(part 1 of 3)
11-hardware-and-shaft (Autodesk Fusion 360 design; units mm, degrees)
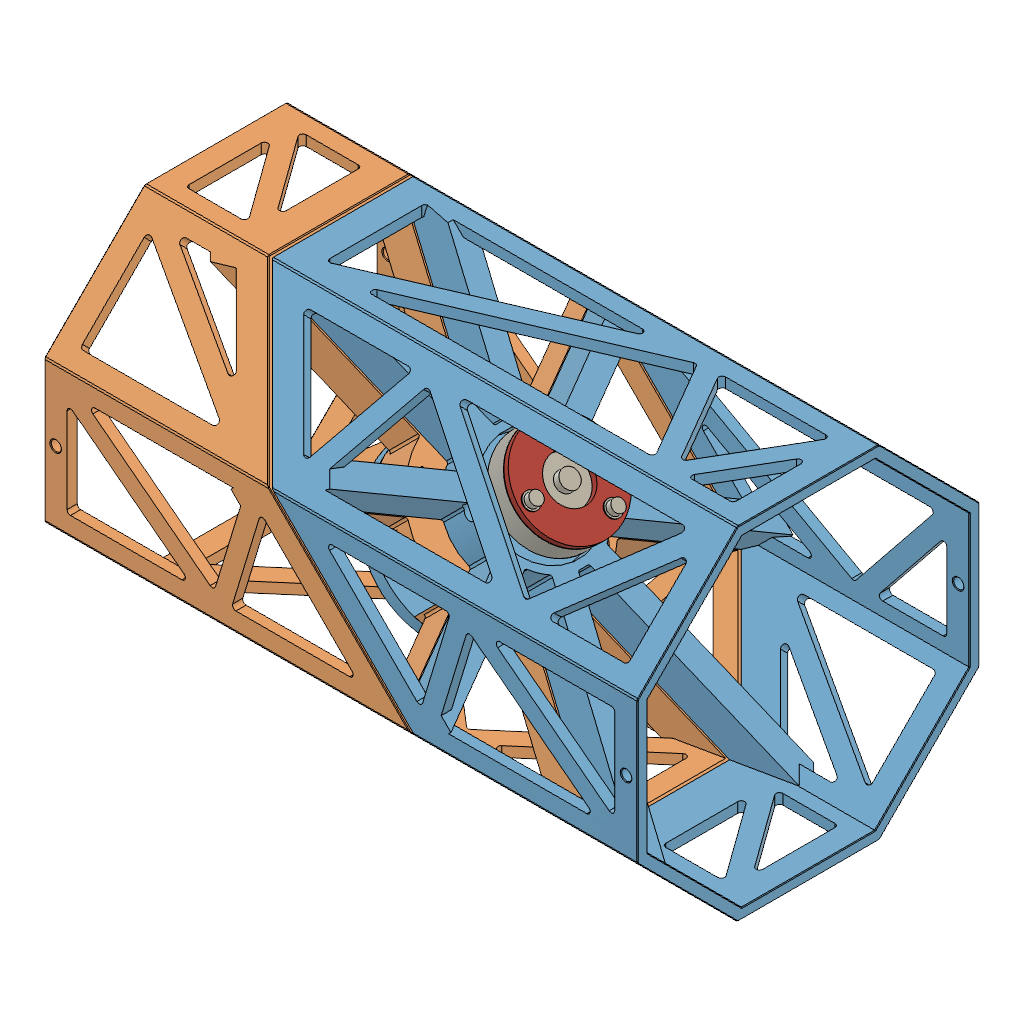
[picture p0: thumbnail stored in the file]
part number: 2026-11-02-20-17-55-344
part number: 2026-11-02-20-17-59-218
part number: 2026-11-02-20-17-59-224
part number: 2026-11-02-20-19-00-695
part number: 2026-11-02-20-19-03-009
part number: 2026-11-02-20-19-04-949
part number: 2026-11-02-20-19-06-912
part number: 2026-11-02-20-19-11-903
part number: 2026-11-02-20-19-12-666
part number: 2026-11-02-20-19-12-978
part number: 2026-11-02-20-19-13-740
part number: 2026-11-02-20-19-14-532
part number: 2026-11-02-20-19-15-361
part number: 2026-11-02-20-19-17-468
part number: 2026-11-02-20-19-19-583
part number: 2026-11-02-20-19-25-638
part number: 2026-11-02-20-19-39-091
parameter "bodyWidth" = 150 comment "Regular octagon across flats; corner diameter is larger."
parameter "bodyLength" = 260 comment "Overall straight length of the shared master blank."
parameter "splitAngle" = 45 comment "Keep this lesson angle at45 degrees."
parameter "faceGap" = 1 comment "Gap between the two printed joint faces."
parameter "wall" = 4.5 comment "Integrated shell and side brace radial thickness."
parameter "faceHalfWidth" = 31.066 (= "bodyWidth * ( sqrt(2) - 1 ) / 2") comment "Half-width of each outer planar facet."
parameter "memberWidth" = 8 comment "Nominal brace and corner chord width in a facet."
parameter "nodeHalfWidth" = 27.066 (= "faceHalfWidth - memberWidth / 2") comment "Chord centerlines measured from facet center."
parameter "jointNodeQ" = 7 comment "First truss skeleton row from the center joint plane."
parameter "endRim" = 10 comment "Uncut axial rim at each distant end."
parameter "endNodeX" = 124 (= "bodyLength / 2 - endRim + memberWidth / 2") comment "Last skeleton row before aperture inset."
parameter "apertureRadius" = 1.5 comment "Rounded internal corners at triangular openings."
parameter "spokeWidth" = 10 comment "Width of each deep bearing bulkhead spoke."
parameter "spokeDepth" = 18 comment "Bulkhead depth normal to the diagonal joint face."
parameter "carrierOD" = 52 comment "Outside of integrated A front bearing carrier."
parameter "rearCarrierClearance" = 46 comment "Internal carrier relief above front bearing shoulder."
parameter "tubeCornerChamfer" = 0.5 comment "Exposed outside octagon corner bevel."
parameter "tubeRimChamfer" = 0.3 comment "End rim and print-contact edge relief."
parameter "cordStation" = 125 (= "bodyLength / 2 - endRim / 2") comment "Load-test cord port center measured along body X."
parameter "bearingOD" = 22 comment "608 measured outside diameter."
parameter "bearingID" = 8 comment "608 bore."
parameter "bearingWidth" = 7 comment "608 width."
parameter "seatAllowance" = 0.2 comment "Trial DIAMETRAL clearance; choose with printed coupon."
parameter "seatDiameter" = 22.2 (= "bearingOD + seatAllowance") comment "Measured fit controls this."
parameter "coreOD" = 44 comment "Bearing holder outer diameter."
parameter "raceRelief" = 19.5 comment "Outer-ring shoulder opening; verify seals."
parameter "frontSeatDepth" = 7.1 comment "0.1 mm outer-ring axial allowance."
parameter "rearSeatDepth" = 7.2 comment "0.2 mm outer-ring axial float."
parameter "shoulder" = 3 comment "Backing behind each bearing seat."
parameter "supportSpacer" = 12 comment "Purchased metal M3 spacer length."
parameter "supportCircle" = 34 comment "Three M3 support bolts."
parameter "supportSpacerOD" = 6 comment "Purchased spacer outside diameter."
parameter "capThickness" = 3 comment "Both printed outer-ring retaining caps."
parameter "m3Clearance" = 3.3 comment "M3 through holes."
parameter "m4Clearance" = 4.3 comment "M4 through holes."
parameter "qFront" = 0.5 (= "faceGap / 2") comment "Front bearing starts at A mating face."
parameter "qFrontBack" = 10.6 (= "qFront + frontSeatDepth + shoulder") comment "End of integrated A holder."
parameter "qRearBase" = 22.6 (= "qFrontBack + supportSpacer") comment "Start of removable rear holder."
parameter "qRearBearing" = 25.6 (= "qRearBase + shoulder") comment "Rear bearing inner end."
parameter "qRearEnd" = 32.8 (= "qRearBearing + rearSeatDepth") comment "Rear holder outer end."
parameter "bearingSpacing" = 25.1 (= "qRearBearing - qFront") comment "Derived support-center spacing, not a bearing rating."
parameter "mountOD" = 76 comment "B mount and F flange outside diameter."
parameter "mountCircle" = 64 comment "Four M4 attachment holes."
parameter "mountOpening" = 50.3 comment "B through opening."
parameter "hubFace" = -23 comment "Metal hub flat mounting face."
parameter "adapterThickness" = 6 comment "F flange and metal compression sleeve length."
parameter "pilotDiameter" = 50 comment "F shallow centering pilot."
parameter "pilotInside" = 34 comment "Clearance around metal hub."
parameter "pilotHeight" = 2 comment "Short pilot only."
parameter "hubHoleSpacing" = 16 comment "Metal Sonic hub square hole spacing."
parameter "sleeveOD" = 8 comment "M4 metal compression sleeves."
parameter "sleeveAllowance" = 0.2 comment "Trial DIAMETRAL sleeve clearance."
parameter "shaftClearance" = 8.5 comment "F clearance hole; not a bearing."
parameter "nutAF" = 7.2 comment "M4 nominal 7 AF nut trial pocket."
parameter "nutDepth" = 4 comment "Open front M4 nut pocket."
parameter "rootRadius" = 1 comment "Hub-to-wall blend."
parameter "entryChamfer" = 0.4 comment "Assembly lead-in."
parameter "bedRelief" = 0.3 comment "Bed-contact edge allowance."
sketch "01 Master Octagon" plane through (0, 0, 0) normal (1, 0, 0) x axis (0, 0, -1)
  line L1 (31.066, 75) -> (75, 31.066)
  line L2 (-31.066, 75) -> (31.066, 75)
  line L3 (-75, 31.066) -> (-31.066, 75)
  line L4 (-75, -31.066) -> (-75, 31.066)
  line L5 (-31.066, -75) -> (-75, -31.066)
  line L6 (31.066, -75) -> (-31.066, -75)
  line L7 (75, -31.066) -> (31.066, -75)
  line L8 (75, 31.066) -> (75, -31.066)
  point P1 (0, 0)
  point P10 (0, 0)
  point P3 (31.066, 75)
  point P8 (31.066, -75)
  coincident P1 P10
  horizontal L2
  dimension "d59" distance P3 P8 = 150 (= "bodyWidth")
extrude "Extrude1" new body sketch "01 Master Octagon" distance 260 (= "bodyLength")
work_plane "WorkPlane1" RotateAngle 45 (= "splitAngle") ExtraOffset 0
split "Split1"
offset_faces "OffsetFaces1" distance -0.5 (= "-faceGap / 2")
offset_faces "OffsetFaces2" distance -0.5 (= "-faceGap / 2")
component_from_bodies "Body->Comp1"
component_from_bodies "Body->Comp2"
shell "Shell1" innerThickness 4.5 (= "wall")
shell "Shell1" innerThickness 4.5 (= "wall")
work_plane "WorkPlane1" RotateAngle -90 ExtraOffset 0
work_plane "WorkPlane2" AlongDistance 75 (= "bodyWidth / 2") ExtraOffset 0
sketch "A Facet 0 Triangle 1" plane through (0, 75, 0) normal (0, 1, 0) x axis (1, 0, 0)
  line L1 (-65.1005, -27.066) -> (-65.1005, 27.066)
  line L2 (60.9665, 27.066) -> (-65.1005, -27.066)
  line L3 (-65.1005, 27.066) -> (60.9665, 27.066)
  line L4 (-61.1005, -20.9953) -> (-61.1005, 23.066)
  line L5 (41.513, 23.066) -> (-61.1005, -20.9953)
  line L6 (-61.1005, 23.066) -> (41.513, 23.066)
  point P1 (0, 0)
  point P2 (-65.1005, 27.066)
  point P3 (-65.1005, -27.066)
  point P4 (60.9665, 27.066)
  dimension "d72" distance P1 P2 = 65.1005 (= "Linear Dimension-2")
  dimension "d73" distance P1 P2 = 27.066 (= "Linear Dimension-3")
  dimension "d74" distance P1 P3 = 65.1005 (= "Linear Dimension-4")
  dimension "d75" distance P1 P3 = 27.066 (= "Linear Dimension-5")
  dimension "d76" distance P1 P4 = 60.9665 (= "Linear Dimension-6")
  dimension "d77" distance P1 P4 = 27.066 (= "Linear Dimension-7")
  dimension "d78" = -4 (= "-memberWidth / 2")
extrude "Extrude1" cut sketch "A Facet 0 Triangle 1" profile of L5 L6 L4 against normal blind 4.7 (magnitude of "-( wall + 0.2 mm )")
sketch "A Facet 0 Triangle 2" plane through (0, 75, 0) normal (0, 1, 0) x axis (1, 0, 0)
  line L1 (60.9665, 27.066) -> (-65.1005, -27.066)
  line L2 (92.4832, -27.066) -> (60.9665, 27.066)
  line L3 (-65.1005, -27.066) -> (92.4832, -27.066)
  line L4 (59.2912, 21.9935) -> (-45.647, -23.066)
  line L5 (85.5258, -23.066) -> (59.2912, 21.9935)
  line L6 (-45.647, -23.066) -> (85.5258, -23.066)
  point P1 (0, 0)
  point P2 (-65.1005, -27.066)
  point P3 (60.9665, 27.066)
  point P4 (92.4832, -27.066)
  dimension "d81" distance P1 P2 = 65.1005 (= "Linear Dimension-2")
  dimension "d82" distance P1 P2 = 27.066 (= "Linear Dimension-3")
  dimension "d83" distance P1 P3 = 60.9665 (= "Linear Dimension-4")
  dimension "d84" distance P1 P3 = 27.066 (= "Linear Dimension-5")
  dimension "d85" distance P1 P4 = 92.4832 (= "Linear Dimension-6")
  dimension "d86" distance P1 P4 = 27.066 (= "Linear Dimension-7")
  dimension "d87" = 4 (= "memberWidth / 2")
extrude "Extrude2" cut sketch "A Facet 0 Triangle 2" profile of L5 L6 L4 against normal blind 4.7 (magnitude of "-( wall + 0.2 mm )")
sketch "A Facet 0 Triangle 3" plane through (0, 75, 0) normal (0, 1, 0) x axis (1, 0, 0)
  line L1 (92.4832, -27.066) -> (60.9665, 27.066)
  line L2 (124, 27.066) -> (92.4832, -27.066)
  line L3 (60.9665, 27.066) -> (124, 27.066)
  line L4 (92.4832, -19.1161) -> (67.924, 23.066)
  line L5 (117.0425, 23.066) -> (92.4832, -19.1161)
  line L6 (67.924, 23.066) -> (117.0425, 23.066)
  point P1 (0, 0)
  point P2 (60.9665, 27.066)
  point P3 (92.4832, -27.066)
  point P4 (124, 27.066)
  dimension "d90" distance P1 P2 = 60.9665 (= "Linear Dimension-2")
  dimension "d91" distance P1 P2 = 27.066 (= "Linear Dimension-3")
  dimension "d92" distance P1 P3 = 92.4832 (= "Linear Dimension-4")
  dimension "d93" distance P1 P3 = 27.066 (= "Linear Dimension-5")
  dimension "d94" distance P1 P4 = 124 (= "Linear Dimension-6")
  dimension "d95" distance P1 P4 = 27.066 (= "Linear Dimension-7")
  dimension "d96" = -4 (= "-memberWidth / 2")
extrude "Extrude3" cut sketch "A Facet 0 Triangle 3" profile of L5 L6 L4 against normal blind 4.7 (magnitude of "-( wall + 0.2 mm )")
sketch "A Facet 0 Triangle 4" plane through (0, 75, 0) normal (0, 1, 0) x axis (1, 0, 0)
  line L1 (124, 27.066) -> (92.4832, -27.066)
  line L2 (124, -27.066) -> (124, 27.066)
  line L3 (92.4832, -27.066) -> (124, -27.066)
  line L4 (120, 12.2459) -> (99.4407, -23.066)
  line L5 (120, -23.066) -> (120, 12.2459)
  line L6 (99.4407, -23.066) -> (120, -23.066)
  point P1 (0, 0)
  point P2 (92.4832, -27.066)
  point P3 (124, 27.066)
  point P4 (124, -27.066)
  dimension "d99" distance P1 P2 = 92.4832 (= "Linear Dimension-2")
  dimension "d100" distance P1 P2 = 27.066 (= "Linear Dimension-3")
  dimension "d101" distance P1 P3 = 124 (= "Linear Dimension-4")
  dimension "d102" distance P1 P3 = 27.066 (= "Linear Dimension-5")
  dimension "d103" distance P1 P4 = 124 (= "Linear Dimension-6")
  dimension "d104" distance P1 P4 = 27.066 (= "Linear Dimension-7")
  dimension "d105" = 4 (= "memberWidth / 2")
extrude "Extrude4" cut sketch "A Facet 0 Triangle 4" profile of L5 L6 L4 against normal blind 4.7 (magnitude of "-( wall + 0.2 mm )")
fillet "Fillet1" radius 1.5 (= "apertureRadius")
work_plane "WorkPlane3" RotateAngle -45 ExtraOffset 0
work_plane "WorkPlane4" AlongDistance 75 (= "bodyWidth / 2") ExtraOffset 0
sketch "A Facet 45 Triangle 1" plane through (0, 53.033, 53.033) normal (0, 0.7071, 0.7071) x axis (1, 0, 0)
  line L1 (-23.9949, -27.066) -> (-62.2721, 27.066)
  line L2 (-0.1814, 27.066) -> (-23.9949, -27.066)
  line L3 (-62.2721, 27.066) -> (-0.1814, 27.066)
  line L4 (-24.81, -18.9852) -> (-54.5447, 23.066)
  line L5 (-6.311, 23.066) -> (-24.81, -18.9852)
  line L6 (-54.5447, 23.066) -> (-6.311, 23.066)
  point P1 (0, 0)
  point P2 (-62.2721, 27.066)
  point P3 (-23.9949, -27.066)
  point P4 (-0.1814, 27.066)
  dimension "d114" distance P1 P2 = 62.2721 (= "Linear Dimension-2")
  dimension "d115" distance P1 P2 = 27.066 (= "Linear Dimension-3")
  dimension "d116" distance P1 P3 = 23.9949 (= "Linear Dimension-4")
  dimension "d117" distance P1 P3 = 27.066 (= "Linear Dimension-5")
  dimension "d118" distance P1 P4 = 0.1814 (= "Linear Dimension-6")
  dimension "d119" distance P1 P4 = 27.066 (= "Linear Dimension-7")
  dimension "d120" = -4 (= "-memberWidth / 2")
extrude "Extrude5" cut sketch "A Facet 45 Triangle 1" profile of L5 L6 L4 against normal blind 4.7 (magnitude of "-( wall + 0.2 mm )")
sketch "A Facet 45 Triangle 2" plane through (0, 53.033, 53.033) normal (0, 0.7071, 0.7071) x axis (1, 0, 0)
  line L1 (-0.1814, 27.066) -> (-23.9949, -27.066)
  line L2 (74.6684, -27.066) -> (-0.1814, 27.066)
  line L3 (-23.9949, -27.066) -> (74.6684, -27.066)
  line L4 (1.4863, 20.9235) -> (-17.8653, -23.066)
  line L5 (62.3117, -23.066) -> (1.4863, 20.9235)
  line L6 (-17.8653, -23.066) -> (62.3117, -23.066)
  point P1 (0, 0)
  point P2 (-23.9949, -27.066)
  point P3 (-0.1814, 27.066)
  point P4 (74.6684, -27.066)
  dimension "d123" distance P1 P2 = 23.9949 (= "Linear Dimension-2")
  dimension "d124" distance P1 P2 = 27.066 (= "Linear Dimension-3")
  dimension "d125" distance P1 P3 = 0.1814 (= "Linear Dimension-4")
  dimension "d126" distance P1 P3 = 27.066 (= "Linear Dimension-5")
  dimension "d127" distance P1 P4 = 74.6684 (= "Linear Dimension-6")
  dimension "d128" distance P1 P4 = 27.066 (= "Linear Dimension-7")
  dimension "d129" = 4 (= "memberWidth / 2")
extrude "Extrude6" cut sketch "A Facet 45 Triangle 2" profile of L5 L6 L4 against normal blind 4.7 (magnitude of "-( wall + 0.2 mm )")
sketch "A Facet 45 Triangle 3" plane through (0, 53.033, 53.033) normal (0, 0.7071, 0.7071) x axis (1, 0, 0)
  line L1 (74.6684, -27.066) -> (-0.1814, 27.066)
  line L2 (124, 27.066) -> (74.6684, -27.066)
  line L3 (-0.1814, 27.066) -> (124, 27.066)
  line L4 (74.1179, -21.7315) -> (12.1753, 23.066)
  line L5 (114.9429, 23.066) -> (74.1179, -21.7315)
  line L6 (12.1753, 23.066) -> (114.9429, 23.066)
  point P1 (0, 0)
  point P2 (-0.1814, 27.066)
  point P3 (74.6684, -27.066)
  point P4 (124, 27.066)
  dimension "d132" distance P1 P2 = 0.1814 (= "Linear Dimension-2")
  dimension "d133" distance P1 P2 = 27.066 (= "Linear Dimension-3")
  dimension "d134" distance P1 P3 = 74.6684 (= "Linear Dimension-4")
  dimension "d135" distance P1 P3 = 27.066 (= "Linear Dimension-5")
  dimension "d136" distance P1 P4 = 124 (= "Linear Dimension-6")
  dimension "d137" distance P1 P4 = 27.066 (= "Linear Dimension-7")
  dimension "d138" = -4 (= "-memberWidth / 2")
extrude "Extrude7" cut sketch "A Facet 45 Triangle 3" profile of L5 L6 L4 against normal blind 4.7 (magnitude of "-( wall + 0.2 mm )")
sketch "A Facet 45 Triangle 4" plane through (0, 53.033, 53.033) normal (0, 0.7071, 0.7071) x axis (1, 0, 0)
  line L1 (124, 27.066) -> (74.6684, -27.066)
  line L2 (124, -27.066) -> (124, 27.066)
  line L3 (74.6684, -27.066) -> (124, -27.066)
  line L4 (120, 16.7383) -> (83.7255, -23.066)
  line L5 (120, -23.066) -> (120, 16.7383)
  line L6 (83.7255, -23.066) -> (120, -23.066)
  point P1 (0, 0)
  point P2 (74.6684, -27.066)
  point P3 (124, 27.066)
  point P4 (124, -27.066)
  dimension "d141" distance P1 P2 = 74.6684 (= "Linear Dimension-2")
  dimension "d142" distance P1 P2 = 27.066 (= "Linear Dimension-3")
  dimension "d143" distance P1 P3 = 124 (= "Linear Dimension-4")
  dimension "d144" distance P1 P3 = 27.066 (= "Linear Dimension-5")
  dimension "d145" distance P1 P4 = 124 (= "Linear Dimension-6")
  dimension "d146" distance P1 P4 = 27.066 (= "Linear Dimension-7")
  dimension "d147" = 4 (= "memberWidth / 2")
extrude "Extrude8" cut sketch "A Facet 45 Triangle 4" profile of L5 L6 L4 against normal blind 4.7 (magnitude of "-( wall + 0.2 mm )")
fillet "Fillet2" radius 1.5 (= "apertureRadius")
work_plane "WorkPlane5" RotateAngle 0 ExtraOffset 0
work_plane "WorkPlane6" AlongDistance 75 (= "bodyWidth / 2") ExtraOffset 0
sketch "A Facet 90 Triangle 1" plane through (0, 0, 75) normal (0, 0, 1) x axis (1, 0, 0)
  line L1 (36.9655, -27.066) -> (-17.1665, 27.066)
  line L2 (53.4167, 27.066) -> (36.9655, -27.066)
  line L3 (-17.1665, 27.066) -> (53.4167, 27.066)
  line L4 (35.0777, -19.5214) -> (-7.5097, 23.066)
  line L5 (48.0205, 23.066) -> (35.0777, -19.5214)
  line L6 (-7.5097, 23.066) -> (48.0205, 23.066)
  point P1 (0, 0)
  point P2 (-17.1665, 27.066)
  point P3 (36.9655, -27.066)
  point P4 (53.4167, 27.066)
  dimension "d156" distance P1 P2 = 17.1665 (= "Linear Dimension-2")
  dimension "d157" distance P1 P2 = 27.066 (= "Linear Dimension-3")
  dimension "d158" distance P1 P3 = 36.9655 (= "Linear Dimension-4")
  dimension "d159" distance P1 P3 = 27.066 (= "Linear Dimension-5")
  dimension "d160" distance P1 P4 = 53.4167 (= "Linear Dimension-6")
  dimension "d161" distance P1 P4 = 27.066 (= "Linear Dimension-7")
  dimension "d162" = -4 (= "-memberWidth / 2")
extrude "Extrude9" cut sketch "A Facet 90 Triangle 1" profile of L5 L6 L4 against normal blind 4.7 (magnitude of "-( wall + 0.2 mm )")
sketch "A Facet 90 Triangle 2" plane through (0, 0, 75) normal (0, 0, 1) x axis (1, 0, 0)
  line L1 (53.4167, 27.066) -> (36.9655, -27.066)
  line L2 (124, -27.066) -> (53.4167, 27.066)
  line L3 (36.9655, -27.066) -> (124, -27.066)
  line L4 (55.5648, 20.3777) -> (42.3618, -23.066)
  line L5 (112.2115, -23.066) -> (55.5648, 20.3777)
  line L6 (42.3618, -23.066) -> (112.2115, -23.066)
  point P1 (0, 0)
  point P2 (36.9655, -27.066)
  point P3 (53.4167, 27.066)
  point P4 (124, -27.066)
  dimension "d165" distance P1 P2 = 36.9655 (= "Linear Dimension-2")
  dimension "d166" distance P1 P2 = 27.066 (= "Linear Dimension-3")
  dimension "d167" distance P1 P3 = 53.4167 (= "Linear Dimension-4")
  dimension "d168" distance P1 P3 = 27.066 (= "Linear Dimension-5")
  dimension "d169" distance P1 P4 = 124 (= "Linear Dimension-6")
  dimension "d170" distance P1 P4 = 27.066 (= "Linear Dimension-7")
  dimension "d171" = 4 (= "memberWidth / 2")
extrude "Extrude10" cut sketch "A Facet 90 Triangle 2" profile of L5 L6 L4 against normal blind 4.7 (magnitude of "-( wall + 0.2 mm )")
sketch "A Facet 90 Triangle 3" plane through (0, 0, 75) normal (0, 0, 1) x axis (1, 0, 0)
  line L1 (124, -27.066) -> (53.4167, 27.066)
  line L2 (124, 27.066) -> (124, -27.066)
  line L3 (53.4167, 27.066) -> (124, 27.066)
  line L4 (120, -18.9574) -> (65.2053, 23.066)
  line L5 (120, 23.066) -> (120, -18.9574)
  line L6 (65.2053, 23.066) -> (120, 23.066)
  point P1 (0, 0)
  point P2 (53.4167, 27.066)
  point P3 (124, -27.066)
  point P4 (124, 27.066)
  dimension "d174" distance P1 P2 = 53.4167 (= "Linear Dimension-2")
  dimension "d175" distance P1 P2 = 27.066 (= "Linear Dimension-3")
  dimension "d176" distance P1 P3 = 124 (= "Linear Dimension-4")
  dimension "d177" distance P1 P3 = 27.066 (= "Linear Dimension-5")
  dimension "d178" distance P1 P4 = 124 (= "Linear Dimension-6")
  dimension "d179" distance P1 P4 = 27.066 (= "Linear Dimension-7")
  dimension "d180" = -4 (= "-memberWidth / 2")
extrude "Extrude11" cut sketch "A Facet 90 Triangle 3" profile of L5 L6 L4 against normal blind 4.7 (magnitude of "-( wall + 0.2 mm )")
fillet "Fillet3" radius 1.5 (= "apertureRadius")
work_plane "WorkPlane7" RotateAngle 45 ExtraOffset 0
work_plane "WorkPlane8" AlongDistance 75 (= "bodyWidth / 2") ExtraOffset 0
sketch "A Facet 135 Triangle 1" plane through (0, -53.033, 53.033) normal (0, -0.7071, 0.7071) x axis (1, 0, 0)
  line L1 (82.0711, -27.066) -> (43.7939, 27.066)
  line L2 (124, 27.066) -> (82.0711, -27.066)
  line L3 (43.7939, 27.066) -> (124, 27.066)
  line L4 (82.2175, -20.3449) -> (51.5213, 23.066)
  line L5 (115.8422, 23.066) -> (82.2175, -20.3449)
  line L6 (51.5213, 23.066) -> (115.8422, 23.066)
  point P1 (0, 0)
  point P2 (43.7939, 27.066)
  point P3 (82.0711, -27.066)
  point P4 (124, 27.066)
  dimension "d189" distance P1 P2 = 43.7939 (= "Linear Dimension-2")
  dimension "d190" distance P1 P2 = 27.066 (= "Linear Dimension-3")
  dimension "d191" distance P1 P3 = 82.0711 (= "Linear Dimension-4")
  dimension "d192" distance P1 P3 = 27.066 (= "Linear Dimension-5")
  dimension "d193" distance P1 P4 = 124 (= "Linear Dimension-6")
  dimension "d194" distance P1 P4 = 27.066 (= "Linear Dimension-7")
  dimension "d195" = -4 (= "-memberWidth / 2")
extrude "Extrude12" cut sketch "A Facet 135 Triangle 1" profile of L5 L6 L4 against normal blind 4.7 (magnitude of "-( wall + 0.2 mm )")
sketch "A Facet 135 Triangle 2" plane through (0, -53.033, 53.033) normal (0, -0.7071, 0.7071) x axis (1, 0, 0)
  line L1 (124, 27.066) -> (82.0711, -27.066)
  line L2 (124, -27.066) -> (124, 27.066)
  line L3 (82.0711, -27.066) -> (124, -27.066)
  line L4 (120, 15.3697) -> (90.2289, -23.066)
  line L5 (120, -23.066) -> (120, 15.3697)
  line L6 (90.2289, -23.066) -> (120, -23.066)
  point P1 (0, 0)
  point P2 (82.0711, -27.066)
  point P3 (124, 27.066)
  point P4 (124, -27.066)
  dimension "d198" distance P1 P2 = 82.0711 (= "Linear Dimension-2")
  dimension "d199" distance P1 P2 = 27.066 (= "Linear Dimension-3")
  dimension "d200" distance P1 P3 = 124 (= "Linear Dimension-4")
  dimension "d201" distance P1 P3 = 27.066 (= "Linear Dimension-5")
  dimension "d202" distance P1 P4 = 124 (= "Linear Dimension-6")
  dimension "d203" distance P1 P4 = 27.066 (= "Linear Dimension-7")
  dimension "d204" = 4 (= "memberWidth / 2")
extrude "Extrude13" cut sketch "A Facet 135 Triangle 2" profile of L5 L6 L4 against normal blind 4.7 (magnitude of "-( wall + 0.2 mm )")
fillet "Fillet4" radius 1.5 (= "apertureRadius")
work_plane "WorkPlane9" RotateAngle 90 ExtraOffset 0
work_plane "WorkPlane10" AlongDistance 75 (= "bodyWidth / 2") ExtraOffset 0
sketch "A Facet 180 Triangle 1" plane through (0, -75, 0) normal (0, -1, 0) x axis (-1, 0, 0)
  line L1 (-84.8995, 27.066) -> (-84.8995, -27.066)
  line L2 (-124, -27.066) -> (-84.8995, 27.066)
  line L3 (-84.8995, -27.066) -> (-124, -27.066)
  line L4 (-88.8995, 14.697) -> (-88.8995, -23.066)
  line L5 (-116.1764, -23.066) -> (-88.8995, 14.697)
  line L6 (-88.8995, -23.066) -> (-116.1764, -23.066)
  point P1 (0, 0)
  point P2 (-84.8995, -27.066)
  point P3 (-84.8995, 27.066)
  point P4 (-124, -27.066)
  dimension "d213" distance P1 P2 = 84.8995 (= "Linear Dimension-2")
  dimension "d214" distance P1 P2 = 27.066 (= "Linear Dimension-3")
  dimension "d215" distance P1 P3 = 84.8995 (= "Linear Dimension-4")
  dimension "d216" distance P1 P3 = 27.066 (= "Linear Dimension-5")
  dimension "d217" distance P1 P4 = 124 (= "Linear Dimension-6")
  dimension "d218" distance P1 P4 = 27.066 (= "Linear Dimension-7")
  dimension "d219" = -4 (= "-memberWidth / 2")
extrude "Extrude14" cut sketch "A Facet 180 Triangle 1" profile of L5 L6 L4 against normal blind 4.7 (magnitude of "-( wall + 0.2 mm )")
sketch "A Facet 180 Triangle 2" plane through (0, -75, 0) normal (0, -1, 0) x axis (-1, 0, 0)
  line L1 (-124, -27.066) -> (-84.8995, 27.066)
  line L2 (-124, 27.066) -> (-124, -27.066)
  line L3 (-84.8995, 27.066) -> (-124, 27.066)
  line L4 (-120, -14.697) -> (-92.7231, 23.066)
  line L5 (-120, 23.066) -> (-120, -14.697)
  line L6 (-92.7231, 23.066) -> (-120, 23.066)
  point P1 (0, 0)
  point P2 (-84.8995, 27.066)
  point P3 (-124, -27.066)
  point P4 (-124, 27.066)
  dimension "d222" distance P1 P2 = 84.8995 (= "Linear Dimension-2")
  dimension "d223" distance P1 P2 = 27.066 (= "Linear Dimension-3")
  dimension "d224" distance P1 P3 = 124 (= "Linear Dimension-4")
  dimension "d225" distance P1 P3 = 27.066 (= "Linear Dimension-5")
  dimension "d226" distance P1 P4 = 124 (= "Linear Dimension-6")
  dimension "d227" distance P1 P4 = 27.066 (= "Linear Dimension-7")
  dimension "d228" = 4 (= "memberWidth / 2")
extrude "Extrude15" cut sketch "A Facet 180 Triangle 2" profile of L5 L6 L4 against normal blind 4.7 (magnitude of "-( wall + 0.2 mm )")
fillet "Fillet5" radius 1.5 (= "apertureRadius")
work_plane "WorkPlane11" RotateAngle 135 ExtraOffset 0
work_plane "WorkPlane12" AlongDistance 75 (= "bodyWidth / 2") ExtraOffset 0
sketch "A Facet 225 Triangle 1" plane through (0, -53.033, -53.033) normal (0, -0.7071, -0.7071) x axis (1, 0, 0)
  line L1 (43.7939, -27.066) -> (82.0711, 27.066)
  line L2 (124, 27.066) -> (43.7939, -27.066)
  line L3 (82.0711, 27.066) -> (124, 27.066)
  line L4 (59.6927, -11.51) -> (84.1416, 23.066)
  line L5 (110.9231, 23.066) -> (59.6927, -11.51)
  line L6 (84.1416, 23.066) -> (110.9231, 23.066)
  point P1 (0, 0)
  point P2 (82.0711, 27.066)
  point P3 (43.7939, -27.066)
  point P4 (124, 27.066)
  dimension "d237" distance P1 P2 = 82.0711 (= "Linear Dimension-2")
  dimension "d238" distance P1 P2 = 27.066 (= "Linear Dimension-3")
  dimension "d239" distance P1 P3 = 43.7939 (= "Linear Dimension-4")
  dimension "d240" distance P1 P3 = 27.066 (= "Linear Dimension-5")
  dimension "d241" distance P1 P4 = 124 (= "Linear Dimension-6")
  dimension "d242" distance P1 P4 = 27.066 (= "Linear Dimension-7")
  dimension "d243" = -4 (= "-memberWidth / 2")
extrude "Extrude16" cut sketch "A Facet 225 Triangle 1" profile of L5 L6 L4 against normal blind 4.7 (magnitude of "-( wall + 0.2 mm )")
sketch "A Facet 225 Triangle 2" plane through (0, -53.033, -53.033) normal (0, -0.7071, -0.7071) x axis (1, 0, 0)
  line L1 (124, 27.066) -> (43.7939, -27.066)
  line L2 (124, -27.066) -> (124, 27.066)
  line L3 (43.7939, -27.066) -> (124, -27.066)
  line L4 (120, 19.5406) -> (56.8709, -23.066)
  line L5 (120, -23.066) -> (120, 19.5406)
  line L6 (56.8709, -23.066) -> (120, -23.066)
  point P1 (0, 0)
  point P2 (43.7939, -27.066)
  point P3 (124, 27.066)
  point P4 (124, -27.066)
  dimension "d246" distance P1 P2 = 43.7939 (= "Linear Dimension-2")
  dimension "d247" distance P1 P2 = 27.066 (= "Linear Dimension-3")
  dimension "d248" distance P1 P3 = 124 (= "Linear Dimension-4")
  dimension "d249" distance P1 P3 = 27.066 (= "Linear Dimension-5")
  dimension "d250" distance P1 P4 = 124 (= "Linear Dimension-6")
  dimension "d251" distance P1 P4 = 27.066 (= "Linear Dimension-7")
  dimension "d252" = 4 (= "memberWidth / 2")
extrude "Extrude17" cut sketch "A Facet 225 Triangle 2" profile of L5 L6 L4 against normal blind 4.7 (magnitude of "-( wall + 0.2 mm )")
fillet "Fillet6" radius 1.5 (= "apertureRadius")
work_plane "WorkPlane13" RotateAngle 180 ExtraOffset 0
work_plane "WorkPlane14" AlongDistance 75 (= "bodyWidth / 2") ExtraOffset 0
sketch "A Facet 270 Triangle 1" plane through (0, 0, -75) normal (0, 0, -1) x axis (-1, 0, 0)
  line L1 (17.1665, 27.066) -> (-36.9655, -27.066)
  line L2 (-80.4828, -27.066) -> (17.1665, 27.066)
  line L3 (-36.9655, -27.066) -> (-80.4828, -27.066)
  line L4 (-5.7896, 9.7668) -> (-38.6224, -23.066)
  line L5 (-65.0169, -23.066) -> (-5.7896, 9.7668)
  line L6 (-38.6224, -23.066) -> (-65.0169, -23.066)
  point P1 (0, 0)
  point P2 (-36.9655, -27.066)
  point P3 (17.1665, 27.066)
  point P4 (-80.4828, -27.066)
  dimension "d261" distance P1 P2 = 36.9655 (= "Linear Dimension-2")
  dimension "d262" distance P1 P2 = 27.066 (= "Linear Dimension-3")
  dimension "d263" distance P1 P3 = 17.1665 (= "Linear Dimension-4")
  dimension "d264" distance P1 P3 = 27.066 (= "Linear Dimension-5")
  dimension "d265" distance P1 P4 = 80.4828 (= "Linear Dimension-6")
  dimension "d266" distance P1 P4 = 27.066 (= "Linear Dimension-7")
  dimension "d267" = -4 (= "-memberWidth / 2")
extrude "Extrude18" cut sketch "A Facet 270 Triangle 1" profile of L5 L6 L4 against normal blind 4.7 (magnitude of "-( wall + 0.2 mm )")
sketch "A Facet 270 Triangle 2" plane through (0, 0, -75) normal (0, 0, -1) x axis (-1, 0, 0)
  line L1 (-80.4828, -27.066) -> (17.1665, 27.066)
  line L2 (-124, 27.066) -> (-80.4828, -27.066)
  line L3 (17.1665, 27.066) -> (-124, 27.066)
  line L4 (-79.4759, -21.9343) -> (1.7007, 23.066)
  line L5 (-115.6521, 23.066) -> (-79.4759, -21.9343)
  line L6 (1.7007, 23.066) -> (-115.6521, 23.066)
  point P1 (0, 0)
  point P2 (17.1665, 27.066)
  point P3 (-80.4828, -27.066)
  point P4 (-124, 27.066)
  dimension "d270" distance P1 P2 = 17.1665 (= "Linear Dimension-2")
  dimension "d271" distance P1 P2 = 27.066 (= "Linear Dimension-3")
  dimension "d272" distance P1 P3 = 80.4828 (= "Linear Dimension-4")
  dimension "d273" distance P1 P3 = 27.066 (= "Linear Dimension-5")
  dimension "d274" distance P1 P4 = 124 (= "Linear Dimension-6")
  dimension "d275" distance P1 P4 = 27.066 (= "Linear Dimension-7")
  dimension "d276" = 4 (= "memberWidth / 2")
extrude "Extrude19" cut sketch "A Facet 270 Triangle 2" profile of L5 L6 L4 against normal blind 4.7 (magnitude of "-( wall + 0.2 mm )")
sketch "A Facet 270 Triangle 3" plane through (0, 0, -75) normal (0, 0, -1) x axis (-1, 0, 0)
  line L1 (-124, 27.066) -> (-80.4828, -27.066)
  line L2 (-124, -27.066) -> (-124, 27.066)
  line L3 (-80.4828, -27.066) -> (-124, -27.066)
  line L4 (-120, 15.7062) -> (-88.8307, -23.066)
  line L5 (-120, -23.066) -> (-120, 15.7062)
  line L6 (-88.8307, -23.066) -> (-120, -23.066)
  point P1 (0, 0)
  point P2 (-80.4828, -27.066)
  point P3 (-124, 27.066)
  point P4 (-124, -27.066)
  dimension "d279" distance P1 P2 = 80.4828 (= "Linear Dimension-2")
  dimension "d280" distance P1 P2 = 27.066 (= "Linear Dimension-3")
  dimension "d281" distance P1 P3 = 124 (= "Linear Dimension-4")
  dimension "d282" distance P1 P3 = 27.066 (= "Linear Dimension-5")
  dimension "d283" distance P1 P4 = 124 (= "Linear Dimension-6")
  dimension "d284" distance P1 P4 = 27.066 (= "Linear Dimension-7")
  dimension "d285" = -4 (= "-memberWidth / 2")
extrude "Extrude20" cut sketch "A Facet 270 Triangle 3" profile of L5 L6 L4 against normal blind 4.7 (magnitude of "-( wall + 0.2 mm )")
fillet "Fillet7" radius 1.5 (= "apertureRadius")
work_plane "WorkPlane15" RotateAngle 225 ExtraOffset 0
work_plane "WorkPlane16" AlongDistance 75 (= "bodyWidth / 2") ExtraOffset 0
sketch "A Facet 315 Triangle 1" plane through (0, 53.033, -53.033) normal (0, 0.7071, -0.7071) x axis (1, 0, 0)
  line L1 (-62.2721, -27.066) -> (-23.9949, 27.066)
  line L2 (25.3367, 27.066) -> (-62.2721, -27.066)
  line L3 (-23.9949, 27.066) -> (25.3367, 27.066)
  line L4 (-47.6674, -13.34) -> (-21.9244, 23.066)
  line L5 (11.2532, 23.066) -> (-47.6674, -13.34)
  line L6 (-21.9244, 23.066) -> (11.2532, 23.066)
  point P1 (0, 0)
  point P2 (-23.9949, 27.066)
  point P3 (-62.2721, -27.066)
  point P4 (25.3367, 27.066)
  dimension "d294" distance P1 P2 = 23.9949 (= "Linear Dimension-2")
  dimension "d295" distance P1 P2 = 27.066 (= "Linear Dimension-3")
  dimension "d296" distance P1 P3 = 62.2721 (= "Linear Dimension-4")
  dimension "d297" distance P1 P3 = 27.066 (= "Linear Dimension-5")
  dimension "d298" distance P1 P4 = 25.3367 (= "Linear Dimension-6")
  dimension "d299" distance P1 P4 = 27.066 (= "Linear Dimension-7")
  dimension "d300" = -4 (= "-memberWidth / 2")
extrude "Extrude21" cut sketch "A Facet 315 Triangle 1" profile of L5 L6 L4 against normal blind 4.7 (magnitude of "-( wall + 0.2 mm )")
sketch "A Facet 315 Triangle 2" plane through (0, 53.033, -53.033) normal (0, 0.7071, -0.7071) x axis (1, 0, 0)
  line L1 (25.3367, 27.066) -> (-62.2721, -27.066)
  line L2 (61.9093, -27.066) -> (25.3367, 27.066)
  line L3 (-62.2721, -27.066) -> (61.9093, -27.066)
  line L4 (24.1722, 21.6445) -> (-48.1886, -23.066)
  line L5 (54.3795, -23.066) -> (24.1722, 21.6445)
  line L6 (-48.1886, -23.066) -> (54.3795, -23.066)
  point P1 (0, 0)
  point P2 (-62.2721, -27.066)
  point P3 (25.3367, 27.066)
  point P4 (61.9093, -27.066)
  dimension "d303" distance P1 P2 = 62.2721 (= "Linear Dimension-2")
  dimension "d304" distance P1 P2 = 27.066 (= "Linear Dimension-3")
  dimension "d305" distance P1 P3 = 25.3367 (= "Linear Dimension-4")
  dimension "d306" distance P1 P3 = 27.066 (= "Linear Dimension-5")
  dimension "d307" distance P1 P4 = 61.9093 (= "Linear Dimension-6")
  dimension "d308" distance P1 P4 = 27.066 (= "Linear Dimension-7")
  dimension "d309" = 4 (= "memberWidth / 2")
extrude "Extrude22" cut sketch "A Facet 315 Triangle 2" profile of L5 L6 L4 against normal blind 4.7 (magnitude of "-( wall + 0.2 mm )")
sketch "A Facet 315 Triangle 3" plane through (0, 53.033, -53.033) normal (0, 0.7071, -0.7071) x axis (1, 0, 0)
  line L1 (61.9093, -27.066) -> (25.3367, 27.066)
  line L2 (124, 27.066) -> (61.9093, -27.066)
  line L3 (25.3367, 27.066) -> (124, 27.066)
  line L4 (62.6909, -21.0779) -> (32.8665, 23.066)
  line L5 (113.325, 23.066) -> (62.6909, -21.0779)
  line L6 (32.8665, 23.066) -> (113.325, 23.066)
  point P1 (0, 0)
  point P2 (25.3367, 27.066)
  point P3 (61.9093, -27.066)
  point P4 (124, 27.066)
  dimension "d312" distance P1 P2 = 25.3367 (= "Linear Dimension-2")
  dimension "d313" distance P1 P2 = 27.066 (= "Linear Dimension-3")
  dimension "d314" distance P1 P3 = 61.9093 (= "Linear Dimension-4")
  dimension "d315" distance P1 P3 = 27.066 (= "Linear Dimension-5")
  dimension "d316" distance P1 P4 = 124 (= "Linear Dimension-6")
  dimension "d317" distance P1 P4 = 27.066 (= "Linear Dimension-7")
  dimension "d318" = -4 (= "-memberWidth / 2")
extrude "Extrude23" cut sketch "A Facet 315 Triangle 3" profile of L5 L6 L4 against normal blind 4.7 (magnitude of "-( wall + 0.2 mm )")
sketch "A Facet 315 Triangle 4" plane through (0, 53.033, -53.033) normal (0, 0.7071, -0.7071) x axis (1, 0, 0)
  line L1 (124, 27.066) -> (61.9093, -27.066)
  line L2 (124, -27.066) -> (124, 27.066)
  line L3 (61.9093, -27.066) -> (124, -27.066)
  line L4 (120, 18.272) -> (72.5843, -23.066)
  line L5 (120, -23.066) -> (120, 18.272)
  line L6 (72.5843, -23.066) -> (120, -23.066)
  point P1 (0, 0)
  point P2 (61.9093, -27.066)
  point P3 (124, 27.066)
  point P4 (124, -27.066)
  dimension "d321" distance P1 P2 = 61.9093 (= "Linear Dimension-2")
  dimension "d322" distance P1 P2 = 27.066 (= "Linear Dimension-3")
  dimension "d323" distance P1 P3 = 124 (= "Linear Dimension-4")
  dimension "d324" distance P1 P3 = 27.066 (= "Linear Dimension-5")
  dimension "d325" distance P1 P4 = 124 (= "Linear Dimension-6")
  dimension "d326" distance P1 P4 = 27.066 (= "Linear Dimension-7")
  dimension "d327" = 4 (= "memberWidth / 2")
extrude "Extrude24" cut sketch "A Facet 315 Triangle 4" profile of L5 L6 L4 against normal blind 4.7 (magnitude of "-( wall + 0.2 mm )")
fillet "Fillet8" radius 1.5 (= "apertureRadius")
work_plane "WorkPlane1" RotateAngle -90 ExtraOffset 0
work_plane "WorkPlane2" AlongDistance 75 (= "bodyWidth / 2") ExtraOffset 0
sketch "B Facet 0 Triangle 1" plane through (0, 75, 0) normal (0, 1, 0) x axis (1, 0, 0)
  line L1 (-84.8995, -27.066) -> (-84.8995, 27.066)
  line L2 (-124, 27.066) -> (-84.8995, -27.066)
  line L3 (-84.8995, 27.066) -> (-124, 27.066)
  line L4 (-88.8995, -14.697) -> (-88.8995, 23.066)
  line L5 (-116.1764, 23.066) -> (-88.8995, -14.697)
  line L6 (-88.8995, 23.066) -> (-116.1764, 23.066)
  point P1 (0, 0)
  point P2 (-84.8995, 27.066)
  point P3 (-84.8995, -27.066)
  point P4 (-124, 27.066)
  dimension "d336" distance P1 P2 = 84.8995 (= "Linear Dimension-2")
  dimension "d337" distance P1 P2 = 27.066 (= "Linear Dimension-3")
  dimension "d338" distance P1 P3 = 84.8995 (= "Linear Dimension-4")
  dimension "d339" distance P1 P3 = 27.066 (= "Linear Dimension-5")
  dimension "d340" distance P1 P4 = 124 (= "Linear Dimension-6")
  dimension "d341" distance P1 P4 = 27.066 (= "Linear Dimension-7")
  dimension "d342" = 4 (= "memberWidth / 2")
extrude "Extrude1" cut sketch "B Facet 0 Triangle 1" profile of L5 L6 L4 against normal blind 4.7 (magnitude of "-( wall + 0.2 mm )")
sketch "B Facet 0 Triangle 2" plane through (0, 75, 0) normal (0, 1, 0) x axis (1, 0, 0)
  line L1 (-124, 27.066) -> (-84.8995, -27.066)
  line L2 (-124, -27.066) -> (-124, 27.066)
  line L3 (-84.8995, -27.066) -> (-124, -27.066)
  line L4 (-120, 14.697) -> (-92.7231, -23.066)
  line L5 (-120, -23.066) -> (-120, 14.697)
  line L6 (-92.7231, -23.066) -> (-120, -23.066)
  point P1 (0, 0)
  point P2 (-84.8995, -27.066)
  point P3 (-124, 27.066)
  point P4 (-124, -27.066)
  dimension "d345" distance P1 P2 = 84.8995 (= "Linear Dimension-2")
  dimension "d346" distance P1 P2 = 27.066 (= "Linear Dimension-3")
  dimension "d347" distance P1 P3 = 124 (= "Linear Dimension-4")
  dimension "d348" distance P1 P3 = 27.066 (= "Linear Dimension-5")
  dimension "d349" distance P1 P4 = 124 (= "Linear Dimension-6")
  dimension "d350" distance P1 P4 = 27.066 (= "Linear Dimension-7")
  dimension "d351" = -4 (= "-memberWidth / 2")
extrude "Extrude2" cut sketch "B Facet 0 Triangle 2" profile of L5 L6 L4 against normal blind 4.7 (magnitude of "-( wall + 0.2 mm )")
fillet "Fillet1" radius 1.5 (= "apertureRadius")
work_plane "WorkPlane3" RotateAngle -45 ExtraOffset 0
work_plane "WorkPlane4" AlongDistance 75 (= "bodyWidth / 2") ExtraOffset 0
sketch "B Facet 45 Triangle 1" plane through (0, 53.033, 53.033) normal (0, 0.7071, 0.7071) x axis (1, 0, 0)
  line L1 (-43.7939, -27.066) -> (-82.0711, 27.066)
  line L2 (-124, 27.066) -> (-43.7939, -27.066)
  line L3 (-82.0711, 27.066) -> (-124, 27.066)
  line L4 (-59.6927, -11.51) -> (-84.1416, 23.066)
  line L5 (-110.9231, 23.066) -> (-59.6927, -11.51)
  line L6 (-84.1416, 23.066) -> (-110.9231, 23.066)
  point P1 (0, 0)
  point P2 (-82.0711, 27.066)
  point P3 (-43.7939, -27.066)
  point P4 (-124, 27.066)
  dimension "d360" distance P1 P2 = 82.0711 (= "Linear Dimension-2")
  dimension "d361" distance P1 P2 = 27.066 (= "Linear Dimension-3")
  dimension "d362" distance P1 P3 = 43.7939 (= "Linear Dimension-4")
  dimension "d363" distance P1 P3 = 27.066 (= "Linear Dimension-5")
  dimension "d364" distance P1 P4 = 124 (= "Linear Dimension-6")
  dimension "d365" distance P1 P4 = 27.066 (= "Linear Dimension-7")
  dimension "d366" = 4 (= "memberWidth / 2")
extrude "Extrude3" cut sketch "B Facet 45 Triangle 1" profile of L5 L6 L4 against normal blind 4.7 (magnitude of "-( wall + 0.2 mm )")
sketch "B Facet 45 Triangle 2" plane through (0, 53.033, 53.033) normal (0, 0.7071, 0.7071) x axis (1, 0, 0)
  line L1 (-124, 27.066) -> (-43.7939, -27.066)
  line L2 (-124, -27.066) -> (-124, 27.066)
  line L3 (-43.7939, -27.066) -> (-124, -27.066)
  line L4 (-120, 19.5406) -> (-56.8709, -23.066)
  line L5 (-120, -23.066) -> (-120, 19.5406)
  line L6 (-56.8709, -23.066) -> (-120, -23.066)
  point P1 (0, 0)
  point P2 (-43.7939, -27.066)
  point P3 (-124, 27.066)
  point P4 (-124, -27.066)
  dimension "d369" distance P1 P2 = 43.7939 (= "Linear Dimension-2")
  dimension "d370" distance P1 P2 = 27.066 (= "Linear Dimension-3")
  dimension "d371" distance P1 P3 = 124 (= "Linear Dimension-4")
  dimension "d372" distance P1 P3 = 27.066 (= "Linear Dimension-5")
  dimension "d373" distance P1 P4 = 124 (= "Linear Dimension-6")
  dimension "d374" distance P1 P4 = 27.066 (= "Linear Dimension-7")
  dimension "d375" = -4 (= "-memberWidth / 2")
extrude "Extrude4" cut sketch "B Facet 45 Triangle 2" profile of L5 L6 L4 against normal blind 4.7 (magnitude of "-( wall + 0.2 mm )")
fillet "Fillet2" radius 1.5 (= "apertureRadius")
work_plane "WorkPlane5" RotateAngle 0 ExtraOffset 0
work_plane "WorkPlane6" AlongDistance 75 (= "bodyWidth / 2") ExtraOffset 0
sketch "B Facet 90 Triangle 1" plane through (0, 0, 75) normal (0, 0, 1) x axis (1, 0, 0)
  line L1 (-36.9655, 27.066) -> (17.1665, -27.066)
  line L2 (-53.4167, -27.066) -> (-36.9655, 27.066)
  line L3 (17.1665, -27.066) -> (-53.4167, -27.066)
  line L4 (-35.0777, 19.5214) -> (7.5097, -23.066)
  line L5 (-48.0205, -23.066) -> (-35.0777, 19.5214)
  line L6 (7.5097, -23.066) -> (-48.0205, -23.066)
  point P1 (0, 0)
  point P2 (17.1665, -27.066)
  point P3 (-36.9655, 27.066)
  point P4 (-53.4167, -27.066)
  dimension "d384" distance P1 P2 = 17.1665 (= "Linear Dimension-2")
  dimension "d385" distance P1 P2 = 27.066 (= "Linear Dimension-3")
  dimension "d386" distance P1 P3 = 36.9655 (= "Linear Dimension-4")
  dimension "d387" distance P1 P3 = 27.066 (= "Linear Dimension-5")
  dimension "d388" distance P1 P4 = 53.4167 (= "Linear Dimension-6")
  dimension "d389" distance P1 P4 = 27.066 (= "Linear Dimension-7")
  dimension "d390" = -4 (= "-memberWidth / 2")
extrude "Extrude5" cut sketch "B Facet 90 Triangle 1" profile of L5 L6 L4 against normal blind 4.7 (magnitude of "-( wall + 0.2 mm )")
sketch "B Facet 90 Triangle 2" plane through (0, 0, 75) normal (0, 0, 1) x axis (1, 0, 0)
  line L1 (-53.4167, -27.066) -> (-36.9655, 27.066)
  line L2 (-124, 27.066) -> (-53.4167, -27.066)
  line L3 (-36.9655, 27.066) -> (-124, 27.066)
  line L4 (-55.5648, -20.3777) -> (-42.3618, 23.066)
  line L5 (-112.2115, 23.066) -> (-55.5648, -20.3777)
  line L6 (-42.3618, 23.066) -> (-112.2115, 23.066)
  point P1 (0, 0)
  point P2 (-36.9655, 27.066)
  point P3 (-53.4167, -27.066)
  point P4 (-124, 27.066)
  dimension "d393" distance P1 P2 = 36.9655 (= "Linear Dimension-2")
  dimension "d394" distance P1 P2 = 27.066 (= "Linear Dimension-3")
  dimension "d395" distance P1 P3 = 53.4167 (= "Linear Dimension-4")
  dimension "d396" distance P1 P3 = 27.066 (= "Linear Dimension-5")
  dimension "d397" distance P1 P4 = 124 (= "Linear Dimension-6")
  dimension "d398" distance P1 P4 = 27.066 (= "Linear Dimension-7")
  dimension "d399" = 4 (= "memberWidth / 2")
extrude "Extrude6" cut sketch "B Facet 90 Triangle 2" profile of L5 L6 L4 against normal blind 4.7 (magnitude of "-( wall + 0.2 mm )")
sketch "B Facet 90 Triangle 3" plane through (0, 0, 75) normal (0, 0, 1) x axis (1, 0, 0)
  line L1 (-124, 27.066) -> (-53.4167, -27.066)
  line L2 (-124, -27.066) -> (-124, 27.066)
  line L3 (-53.4167, -27.066) -> (-124, -27.066)
  line L4 (-120, 18.9574) -> (-65.2053, -23.066)
  line L5 (-120, -23.066) -> (-120, 18.9574)
  line L6 (-65.2053, -23.066) -> (-120, -23.066)
  point P1 (0, 0)
  point P2 (-53.4167, -27.066)
  point P3 (-124, 27.066)
  point P4 (-124, -27.066)
  dimension "d402" distance P1 P2 = 53.4167 (= "Linear Dimension-2")
  dimension "d403" distance P1 P2 = 27.066 (= "Linear Dimension-3")
  dimension "d404" distance P1 P3 = 124 (= "Linear Dimension-4")
  dimension "d405" distance P1 P3 = 27.066 (= "Linear Dimension-5")
  dimension "d406" distance P1 P4 = 124 (= "Linear Dimension-6")
  dimension "d407" distance P1 P4 = 27.066 (= "Linear Dimension-7")
  dimension "d408" = -4 (= "-memberWidth / 2")
extrude "Extrude7" cut sketch "B Facet 90 Triangle 3" profile of L5 L6 L4 against normal blind 4.7 (magnitude of "-( wall + 0.2 mm )")
fillet "Fillet3" radius 1.5 (= "apertureRadius")
work_plane "WorkPlane7" RotateAngle 45 ExtraOffset 0
work_plane "WorkPlane8" AlongDistance 75 (= "bodyWidth / 2") ExtraOffset 0
sketch "B Facet 135 Triangle 1" plane through (0, -53.033, 53.033) normal (0, -0.7071, 0.7071) x axis (1, 0, 0)
  line L1 (62.2721, -27.066) -> (23.9949, 27.066)
  line L2 (-25.3367, 27.066) -> (62.2721, -27.066)
  line L3 (23.9949, 27.066) -> (-25.3367, 27.066)
  line L4 (47.6674, -13.34) -> (21.9244, 23.066)
  line L5 (-11.2532, 23.066) -> (47.6674, -13.34)
  line L6 (21.9244, 23.066) -> (-11.2532, 23.066)
  point P1 (0, 0)
  point P2 (23.9949, 27.066)
  point P3 (62.2721, -27.066)
  point P4 (-25.3367, 27.066)
  dimension "d417" distance P1 P2 = 23.9949 (= "Linear Dimension-2")
  dimension "d418" distance P1 P2 = 27.066 (= "Linear Dimension-3")
  dimension "d419" distance P1 P3 = 62.2721 (= "Linear Dimension-4")
  dimension "d420" distance P1 P3 = 27.066 (= "Linear Dimension-5")
  dimension "d421" distance P1 P4 = 25.3367 (= "Linear Dimension-6")
  dimension "d422" distance P1 P4 = 27.066 (= "Linear Dimension-7")
  dimension "d423" = 4 (= "memberWidth / 2")
extrude "Extrude8" cut sketch "B Facet 135 Triangle 1" profile of L5 L6 L4 against normal blind 4.7 (magnitude of "-( wall + 0.2 mm )")
sketch "B Facet 135 Triangle 2" plane through (0, -53.033, 53.033) normal (0, -0.7071, 0.7071) x axis (1, 0, 0)
  line L1 (-25.3367, 27.066) -> (62.2721, -27.066)
  line L2 (-61.9093, -27.066) -> (-25.3367, 27.066)
  line L3 (62.2721, -27.066) -> (-61.9093, -27.066)
  line L4 (-24.1722, 21.6445) -> (48.1886, -23.066)
  line L5 (-54.3795, -23.066) -> (-24.1722, 21.6445)
  line L6 (48.1886, -23.066) -> (-54.3795, -23.066)
  point P1 (0, 0)
  point P2 (62.2721, -27.066)
  point P3 (-25.3367, 27.066)
  point P4 (-61.9093, -27.066)
  dimension "d426" distance P1 P2 = 62.2721 (= "Linear Dimension-2")
  dimension "d427" distance P1 P2 = 27.066 (= "Linear Dimension-3")
  dimension "d428" distance P1 P3 = 25.3367 (= "Linear Dimension-4")
  dimension "d429" distance P1 P3 = 27.066 (= "Linear Dimension-5")
  dimension "d430" distance P1 P4 = 61.9093 (= "Linear Dimension-6")
  dimension "d431" distance P1 P4 = 27.066 (= "Linear Dimension-7")
  dimension "d432" = -4 (= "-memberWidth / 2")
extrude "Extrude9" cut sketch "B Facet 135 Triangle 2" profile of L5 L6 L4 against normal blind 4.7 (magnitude of "-( wall + 0.2 mm )")
sketch "B Facet 135 Triangle 3" plane through (0, -53.033, 53.033) normal (0, -0.7071, 0.7071) x axis (1, 0, 0)
  line L1 (-61.9093, -27.066) -> (-25.3367, 27.066)
  line L2 (-124, 27.066) -> (-61.9093, -27.066)
  line L3 (-25.3367, 27.066) -> (-124, 27.066)
  line L4 (-62.6909, -21.0779) -> (-32.8665, 23.066)
  line L5 (-113.325, 23.066) -> (-62.6909, -21.0779)
  line L6 (-32.8665, 23.066) -> (-113.325, 23.066)
  point P1 (0, 0)
  point P2 (-25.3367, 27.066)
  point P3 (-61.9093, -27.066)
  point P4 (-124, 27.066)
  dimension "d435" distance P1 P2 = 25.3367 (= "Linear Dimension-2")
  dimension "d436" distance P1 P2 = 27.066 (= "Linear Dimension-3")
  dimension "d437" distance P1 P3 = 61.9093 (= "Linear Dimension-4")
  dimension "d438" distance P1 P3 = 27.066 (= "Linear Dimension-5")
  dimension "d439" distance P1 P4 = 124 (= "Linear Dimension-6")
  dimension "d440" distance P1 P4 = 27.066 (= "Linear Dimension-7")
  dimension "d441" = 4 (= "memberWidth / 2")
extrude "Extrude10" cut sketch "B Facet 135 Triangle 3" profile of L5 L6 L4 against normal blind 4.7 (magnitude of "-( wall + 0.2 mm )")
sketch "B Facet 135 Triangle 4" plane through (0, -53.033, 53.033) normal (0, -0.7071, 0.7071) x axis (1, 0, 0)
  line L1 (-124, 27.066) -> (-61.9093, -27.066)
  line L2 (-124, -27.066) -> (-124, 27.066)
  line L3 (-61.9093, -27.066) -> (-124, -27.066)
  line L4 (-120, 18.272) -> (-72.5843, -23.066)
  line L5 (-120, -23.066) -> (-120, 18.272)
  line L6 (-72.5843, -23.066) -> (-120, -23.066)
  point P1 (0, 0)
  point P2 (-61.9093, -27.066)
  point P3 (-124, 27.066)
  point P4 (-124, -27.066)
  dimension "d444" distance P1 P2 = 61.9093 (= "Linear Dimension-2")
  dimension "d445" distance P1 P2 = 27.066 (= "Linear Dimension-3")
  dimension "d446" distance P1 P3 = 124 (= "Linear Dimension-4")
  dimension "d447" distance P1 P3 = 27.066 (= "Linear Dimension-5")
  dimension "d448" distance P1 P4 = 124 (= "Linear Dimension-6")
  dimension "d449" distance P1 P4 = 27.066 (= "Linear Dimension-7")
  dimension "d450" = -4 (= "-memberWidth / 2")
extrude "Extrude11" cut sketch "B Facet 135 Triangle 4" profile of L5 L6 L4 against normal blind 4.7 (magnitude of "-( wall + 0.2 mm )")
fillet "Fillet4" radius 1.5 (= "apertureRadius")
work_plane "WorkPlane9" RotateAngle 90 ExtraOffset 0
work_plane "WorkPlane10" AlongDistance 75 (= "bodyWidth / 2") ExtraOffset 0
sketch "B Facet 180 Triangle 1" plane through (0, -75, 0) normal (0, -1, 0) x axis (-1, 0, 0)
  line L1 (-65.1005, 27.066) -> (-65.1005, -27.066)
  line L2 (-2.067, -27.066) -> (-65.1005, 27.066)
  line L3 (-65.1005, -27.066) -> (-2.067, -27.066)
  line L4 (-61.1005, 18.3583) -> (-61.1005, -23.066)
  line L5 (-12.8644, -23.066) -> (-61.1005, 18.3583)
  line L6 (-61.1005, -23.066) -> (-12.8644, -23.066)
  point P1 (0, 0)
  point P2 (-65.1005, -27.066)
  point P3 (-65.1005, 27.066)
  point P4 (-2.067, -27.066)
  dimension "d459" distance P1 P2 = 65.1005 (= "Linear Dimension-2")
  dimension "d460" distance P1 P2 = 27.066 (= "Linear Dimension-3")
  dimension "d461" distance P1 P3 = 65.1005 (= "Linear Dimension-4")
  dimension "d462" distance P1 P3 = 27.066 (= "Linear Dimension-5")
  dimension "d463" distance P1 P4 = 2.067 (= "Linear Dimension-6")
  dimension "d464" distance P1 P4 = 27.066 (= "Linear Dimension-7")
  dimension "d465" = 4 (= "memberWidth / 2")
extrude "Extrude12" cut sketch "B Facet 180 Triangle 1" profile of L5 L6 L4 against normal blind 4.7 (magnitude of "-( wall + 0.2 mm )")
sketch "B Facet 180 Triangle 2" plane through (0, -75, 0) normal (0, -1, 0) x axis (-1, 0, 0)
  line L1 (-2.067, -27.066) -> (-65.1005, 27.066)
  line L2 (60.9665, 27.066) -> (-2.067, -27.066)
  line L3 (-65.1005, 27.066) -> (60.9665, 27.066)
  line L4 (-2.067, -21.7934) -> (-54.3031, 23.066)
  line L5 (50.1691, 23.066) -> (-2.067, -21.7934)
  line L6 (-54.3031, 23.066) -> (50.1691, 23.066)
  point P1 (0, 0)
  point P2 (-65.1005, 27.066)
  point P3 (-2.067, -27.066)
  point P4 (60.9665, 27.066)
  dimension "d468" distance P1 P2 = 65.1005 (= "Linear Dimension-2")
  dimension "d469" distance P1 P2 = 27.066 (= "Linear Dimension-3")
  dimension "d470" distance P1 P3 = 2.067 (= "Linear Dimension-4")
  dimension "d471" distance P1 P3 = 27.066 (= "Linear Dimension-5")
  dimension "d472" distance P1 P4 = 60.9665 (= "Linear Dimension-6")
  dimension "d473" distance P1 P4 = 27.066 (= "Linear Dimension-7")
  dimension "d474" = -4 (= "-memberWidth / 2")
extrude "Extrude13" cut sketch "B Facet 180 Triangle 2" profile of L5 L6 L4 against normal blind 4.7 (magnitude of "-( wall + 0.2 mm )")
